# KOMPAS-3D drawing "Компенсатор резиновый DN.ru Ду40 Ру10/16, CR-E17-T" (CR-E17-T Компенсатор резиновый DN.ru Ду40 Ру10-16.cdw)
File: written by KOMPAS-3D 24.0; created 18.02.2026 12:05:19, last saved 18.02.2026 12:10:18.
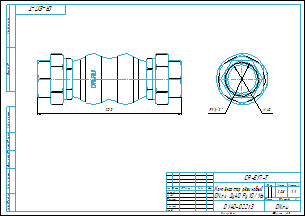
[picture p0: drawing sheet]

Document properties: Типовые: Типовые; Автор: DN.RU; Форматы листов документа: A3; Полное имя файла: CR-E17-T Компенсатор резиновый DN.ru Ду40 Ру10-16.m3d; Масса: 2.08; Наименование: Компенсатор резиновый DN.ru Ду40 Ру10/16; Количество листов документа: 1; Комментарий: D140-02213; Примечание: D140-02213

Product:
- Body: Твердое тело1  | qty 1
    Масса: 2.35583
- Part/product: Компенсатор резиновый DN.ru Ду40 Ру10/16  | designation CR-E17-T
    Масса: 2.08
    Раздел спецификации: Прочие изделия
    Форматы листов документа: A3
    Комментарий: D140-02213
    Примечание: D140-02213
    additional columns: Типовые

Views: Вид 1, Справа, Проекционный вид 2
Referenced files in D:\Работа\Компенсаторы\CR-Е17-T Компенсатор резиновый DN.ru Ду15-80\DN40\: CR-E17-T Компенсатор резиновый DN.ru Ду40 Ру10-16.m3d, CR-E17-T Компенсатор резиновый DN.ru Ду40 Ру10-16.cdw
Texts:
  Линейный размер
  CR-E17-T
  Диаметральный размер
  Компенсатор резиновый
  DN.ru Ду40 Ру10/16
  Твердое тело1
  Компенсатор резиновый DN.ru Ду40 Ру10/16
  CR-E17-T Компенсатор резиновый DN.ru Ду40 Ру10/16
Dimensions and other numbers on the sheet: 0; 3; 2; 4; 200; 40; 1:1; 1; 2,08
